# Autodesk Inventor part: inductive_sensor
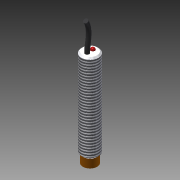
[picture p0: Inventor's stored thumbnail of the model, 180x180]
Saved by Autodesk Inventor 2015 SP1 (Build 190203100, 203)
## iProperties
Created: 2016-05
Part Number: inductive_sensor
Material: Generic
Document SubType Name: Modeling
Designer: Borbon
Density: 1 g/cm^3
Appearance: Dark Gray
Mass: 7.59908 g
Surface Area: 29.0479 cm^2
Volume: 7.59908 cm^3
Author: Borbon
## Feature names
1. Extrusion1
2. Chamfer1
3. Chamfer2
4. Extrusion2
5. Revolution1
6. Sweep1
## Parameters: d0 = 12 mm, d1 = 62 mm, d2 = 0, d4 = 0, d5 = 1 mm, d6 = 2 mm, d7 = 45 deg, d8 = 1 mm, d9 = 2 mm, d10 = 45 deg, d11 = 6 mm, d12 = 0, d13 = 2 mm, d14 = 13 mm, d15 = 6.5 mm, d16 = 3 mm, d17 = 4 mm, d20 = 1.5 mm, d21 = 2 mm, d22 = 90 deg, d23 = 3 mm, d24 = 0, d25 = 0
